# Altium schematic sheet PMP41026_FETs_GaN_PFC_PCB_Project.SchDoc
size 431 x 279 mm; Date: Not shown in title block; ApprovedBy: Not shown in title block; CheckedBy: Not shown in title block; Author: Not shown in title block; CompanyName: Not shown in title block; Engineer: Not shown in title block; Organization: Not shown in title block; Address1: Not shown in title block; Address2: Not shown in title block; Address3: Not shown in title block; Address4: Not shown in title block; DocumentNumber: 2; Revision: Use project parameter SCH_Rev; SheetNumber: 2; SheetTotal: 2; PageSetup: Record=PageOptions¦CenterHorizontal=True¦CenterVertical=True¦PrintScale=1.00¦XCorrection=1.00¦YCorrection=1.00¦PrintKind=0¦BorderSize=5000000¦LeftOffset=0¦BottomOffset=0¦Orientation=2¦PaperLength=1000¦PaperWidth=1000¦Scale=100¦PaperSource=15¦PrintQuality=600¦MediaType=1¦DitherType=10¦PaperKind=Letter¦PrintScaleMode=1
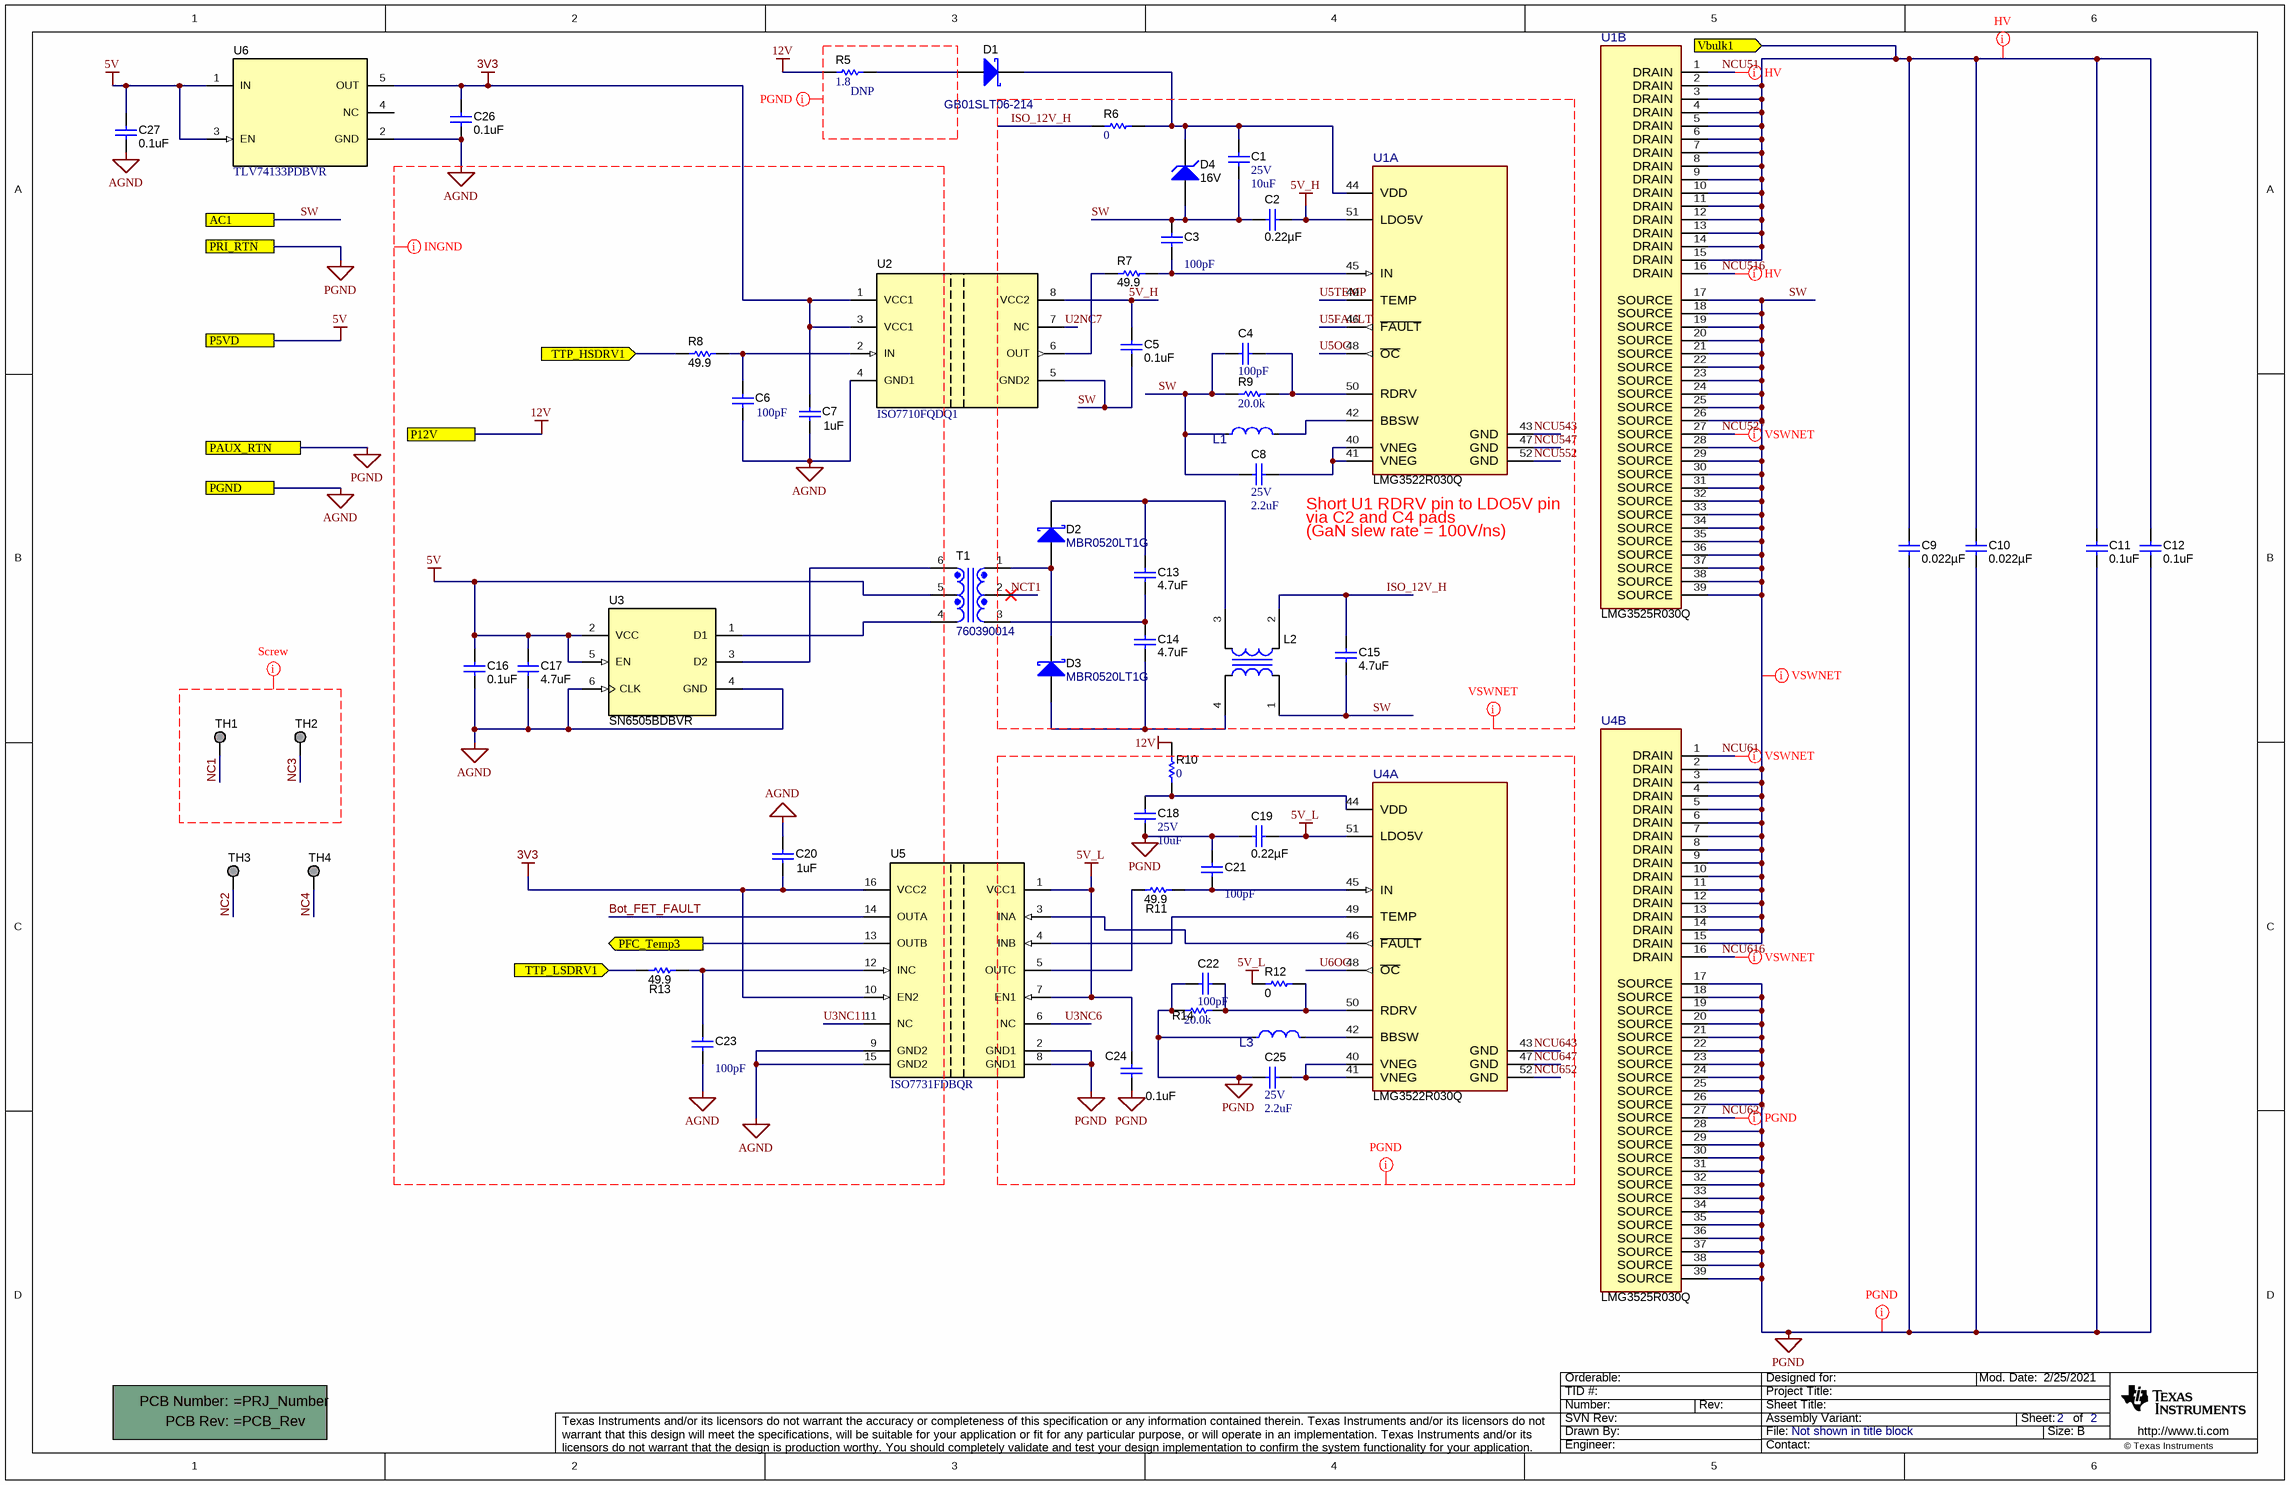
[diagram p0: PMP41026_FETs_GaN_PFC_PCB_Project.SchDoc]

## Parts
!PCB1  Printed Circuit Board  (value not drawn)  (mechanical)
C1  VDC_V: 25V  ValueDisplayed: 10uF  [1206_190]  (hidden comment: C3216X7R1E106M160AE)
C2  ValueDisplayed: 0.22µF  [0402]  (hidden comment: CL05B224KO5NNNC)
C3  ValueDisplayed: 100pF  [0402]  (hidden comment: 04025A101FAT2A)
C4  ValueDisplayed: 100pF  [0402]  (hidden comment: 04025A101FAT2A)
C5  ValueDisplayed: 0.1uF  [0402]  (hidden comment: C1005X7R1H104K050BB)
C6  ValueDisplayed: 100pF  [0402]  (hidden comment: 04025A101FAT2A)
C7  ValueDisplayed: 1uF  [0402]  (hidden comment: C1005X5R1E105K050BC)
C8  VDC_V: 25V  ValueDisplayed: 2.2uF  [0402]  (hidden comment: GRT155R61E225KE13D)
C9  ValueDisplayed: 0.022µF  [1206_190]  (hidden comment: C1206C223KDRACTU)
C10  ValueDisplayed: 0.022µF  [1206_190]  (hidden comment: C1206C223KDRACTU)
C11  ValueDisplayed: 0.1uF  [1812_254]  (hidden comment: C1812W104KDRACTU)
C12  ValueDisplayed: 0.1uF  [1812_254]  (hidden comment: C1812W104KDRACTU)
C13  ValueDisplayed: 4.7uF  [0603]  (hidden comment: C1608X5R1V475K080AC)
C14  ValueDisplayed: 4.7uF  [0603]  (hidden comment: C1608X5R1V475K080AC)
C15  ValueDisplayed: 4.7uF  [0603]  (hidden comment: C1608X5R1V475K080AC)
C16  ValueDisplayed: 0.1uF  [0402]  (hidden comment: C1005X7R1H104K050BB)
C17  ValueDisplayed: 4.7uF  [0805_HV]  (hidden comment: GCM21BR71C475KA73L)
C18  VDC_V: 25V  ValueDisplayed: 10uF  [1206_190]  (hidden comment: C3216X7R1E106M160AE)
C19  ValueDisplayed: 0.22µF  [0402]  (hidden comment: CL05B224KO5NNNC)
C20  ValueDisplayed: 1uF  [0402]  (hidden comment: C1005X5R1E105K050BC)
C21  ValueDisplayed: 100pF  [0402]  (hidden comment: 04025A101FAT2A)
C22  ValueDisplayed: 100pF  [0402]  (hidden comment: 04025A101FAT2A)
C23  ValueDisplayed: 100pF  [0402]  (hidden comment: 04025A101FAT2A)
C24  ValueDisplayed: 0.1uF  [0402]  (hidden comment: C1005X7R1H104K050BB)
C25  VDC_V: 25V  ValueDisplayed: 2.2uF  [0402]  (hidden comment: GRT155R61E225KE13D)
C26  ValueDisplayed: 0.1uF  [0402]  (hidden comment: GRM155R70J104KA01D)
C27  ValueDisplayed: 0.1uF  [0402]  (hidden comment: GRM155R70J104KA01D)
D1  GB01SLT06-214  [SMB]
D2  MBR0520LT1G  [SOD-123]
D3  MBR0520LT1G  [SOD-123]
D4  value 16V  [SOD-123]  (hidden comment: BZT52C16-7-F)
L1  SDEM20161T-4R7MS  [FP-SDEM20161T-4R7MS_SMD2-MFG]  (value not drawn)
L2  ACM2520-601-2P-T002  [TDK_ACM2520-2P]  (value not drawn)
L3  SDEM20161T-4R7MS  [FP-SDEM20161T-4R7MS_SMD2-MFG]  (value not drawn)
R5  ValueDisplayed: 1.8  [1206]  (hidden comment: CRCW12061R80JNEA)  (no BOM)
R6  ValueDisplayed: 0  [0402]  (hidden comment: ERJ-2GE0R00X)
R7  ValueDisplayed: 49.9  [0402]  (hidden comment: RC0402FR-0749R9L)
R8  ValueDisplayed: 49.9  [0402]  (hidden comment: RC0402FR-0749R9L)
R9  ValueDisplayed: 20.0k  [0402]  (hidden comment: CRCW040220K0FKED)
R10  ValueDisplayed: 0  [1206]  (hidden comment: ERJ-8GEY0R00V)
R11  ValueDisplayed: 49.9  [0402]  (hidden comment: RC0402FR-0749R9L)
R12  ValueDisplayed: 0  [0402]  (hidden comment: ERJ-2GE0R00X)  (no BOM)
R13  ValueDisplayed: 49.9  [0402]  (hidden comment: RC0402FR-0749R9L)
R14  ValueDisplayed: 20.0k  [0402]  (hidden comment: CRCW040220K0FKED)
T1  760390014  [Wurth_760390013]
TH1  (no value)  [TP_H045P075]  (no BOM)
TH2  (no value)  [TP_H045P075]  (no BOM)
TH3  (no value)  [TP_H045P075]  (no BOM)
TH4  (no value)  [TP_H045P075]  (no BOM)
U1  LMG3522R030Q  [RQS0052A-MFG]  (parts A,B of 2)
U2  ISO7710FQDQ1  [D0008B_HV]
U3  SN6505BDBVR  [DBV0006A_N]
U4  LMG3522R030Q  [RQS0052A-MFG]  (parts A,B of 2)
U5  ISO7731FDBQR  [DBQ0016A_N]
U6  TLV74133PDBVR  [DBV0005A_N]

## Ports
AC1, P5VD, P12V, PAUX_RTN, PFC_Temp3 (out), PGND, PRI_RTN, TTP_HSDRV1 (in), TTP_LSDRV1 (in), Vbulk1 (in)

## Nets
3V3: C7.1 C20.2 C26.1 U2.1(VCC1) U2.3(VCC1) U5.10(EN2) U5.16(VCC2) U6.5(OUT)
5V: C16.1 C17.1 C27.1 T1.5 U3.2(VCC) U3.5(EN) U6.1(IN) U6.3(EN) ; port P5VD
5V_H: C2.2 C5.1 U1.51(LDO5V) U2.8(VCC2)
5V_L: C19.2 C24.2 R12.1 U4.51(LDO5V) U5.1(VCC1) U5.7(EN1)
12V: R5.1 R10.1 ; port P12V
AGND: C6.2 C7.2 C16.2 C17.2 C20.1 C23.2 C26.2 C27.2 U2.4(GND1) U3.4(GND) U3.6(CLK) U5.9(GND2) U5.15(GND2) U6.2(GND) ; port PGND
PGND: C9.2 C10.2 C11.2 C12.2 C18.2 C19.1 C21.1 C22.1 C24.1 C25.2 L3.1 R14.1 U4.17(SOURCE) U4.18(SOURCE) U4.19(SOURCE) U4.20(SOURCE) U4.21(SOURCE) U4.22(SOURCE) U4.23(SOURCE) U4.24(SOURCE) U4.25(SOURCE) U4.26(SOURCE) U4.28(SOURCE) U4.29(SOURCE) U4.30(SOURCE) U4.31(SOURCE) U4.32(SOURCE) U4.33(SOURCE) U4.34(SOURCE) U4.35(SOURCE) U4.36(SOURCE) U4.37(SOURCE) U4.38(SOURCE) U4.39(SOURCE) U5.2(GND1) U5.8(GND1) ; port PRI_RTN, port PAUX_RTN
Bot_FET_FAULT: U5.14(OUTA)
ISO_12V_H: C15.1 L2.2 R6.1
NC1: TH1.1
NC2: TH3.1
NC3: TH2.1
NC4: TH4.1
NCT1: T1.2
NCU51: U1.1(DRAIN)
NCU61: U4.1(DRAIN)
NCU516: U1.16(DRAIN)
NCU527: U1.27(SOURCE)
NCU543: U1.43(GND)
NCU547: U1.47(GND)
NCU552: U1.52(GND)
NCU616: U4.16(DRAIN)
NCU627: U4.27(SOURCE)
NCU643: U4.43(GND)
NCU647: U4.47(GND)
NCU652: U4.52(GND)
PFC_Temp3: U5.13(OUTB) ; port PFC_Temp3
SW: C1.2 C2.1 C3.1 C4.1 C5.2 C8.2 C15.2 D4.2(A) L1.1 L2.1 R9.1 U1.17(SOURCE) U1.18(SOURCE) U1.19(SOURCE) U1.20(SOURCE) U1.21(SOURCE) U1.22(SOURCE) U1.23(SOURCE) U1.24(SOURCE) U1.25(SOURCE) U1.26(SOURCE) U1.28(SOURCE) U1.29(SOURCE) U1.30(SOURCE) U1.31(SOURCE) U1.32(SOURCE) U1.33(SOURCE) U1.34(SOURCE) U1.35(SOURCE) U1.36(SOURCE) U1.37(SOURCE) U1.38(SOURCE) U1.39(SOURCE) U2.5(GND2) U4.2(DRAIN) U4.3(DRAIN) U4.4(DRAIN) U4.5(DRAIN) U4.6(DRAIN) U4.7(DRAIN) U4.8(DRAIN) U4.9(DRAIN) U4.10(DRAIN) U4.11(DRAIN) U4.12(DRAIN) U4.13(DRAIN) U4.14(DRAIN) U4.15(DRAIN) ; port AC1
TTP_HSDRV1: R8.1 ; port TTP_HSDRV1
TTP_LSDRV1: R13.1 ; port TTP_LSDRV1
U2NC7: U2.7(NC)
U3NC6: U5.6(NC)
U3NC11: U5.11(NC)
U5FAULT: U1.46(~{FAULT})
U5OC: U1.48(~{OC})
U5TEMP: U1.49(TEMP)
U6OC: U4.48(~{OC})
Vbulk1: C9.1 C10.1 C11.1 C12.1 U1.2(DRAIN) U1.3(DRAIN) U1.4(DRAIN) U1.5(DRAIN) U1.6(DRAIN) U1.7(DRAIN) U1.8(DRAIN) U1.9(DRAIN) U1.10(DRAIN) U1.11(DRAIN) U1.12(DRAIN) U1.13(DRAIN) U1.14(DRAIN) U1.15(DRAIN) ; port Vbulk1
NetC1_1: C1.1 D1.1(K) D4.1(K) R6.2 U1.44(VDD)
NetC3_2: C3.2 R7.1 U1.45(IN)
NetC4_2: C4.2 R9.2 U1.50(RDRV)
NetC6_1: C6.1 R8.2 U2.2(IN)
NetC8_1: C8.1 U1.40(VNEG) U1.41(VNEG)
NetC13_1: C13.1 D2.1(K) L2.3
NetC13_2: C13.2 C14.1 T1.3
NetC14_2: C14.2 D3.2(A) L2.4
NetC18_1: C18.1 R10.2 U4.44(VDD)
NetC21_2: C21.2 R11.2 U4.45(IN)
NetC22_2: C22.2 R12.2 R14.2 U4.50(RDRV)
NetC23_1: C23.1 R13.2 U5.12(INC)
NetC25_1: C25.1 U4.40(VNEG) U4.41(VNEG)
NetD1_2: D1.2(A) R5.2
NetD2_2: D2.2(A) D3.1(K) T1.1
NetL1_2: L1.2 U1.42(BBSW)
NetL3_2: L3.2 U4.42(BBSW)
NetR7_2: R7.2 U2.6(OUT)
NetR11_1: R11.1 U5.5(OUTC)
NetT1_4: T1.4 U3.1(D1)
NetT1_6: T1.6 U3.3(D2)
NetU4_46: U4.46(~{FAULT}) U5.3(INA)
NetU4_49: U4.49(TEMP) U5.4(INB)

Not connected (* = marked no-connect by the designer): U6 4(NC)

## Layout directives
net class INGND: 3V3, 5V, 12V, AGND, Bot_FET_FAULT, U3NC11
net class VSWNET: 5V_H, ISO_12V_H, NCT1, NCU61, NCU527, NCU543, NCU547, NCU552, NCU616, SW, U2NC7, U5FAULT, U5OC, U5TEMP
net class PGND: 5V_L, (no net found under the mark), NCU627, NCU643, NCU647, NCU652, PGND, U3NC6, U6OC
net class Screw: NC1, NC3
net class HV: NCU51, NCU516, Vbulk1

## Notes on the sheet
- (near R5) DNP
- Short U1 RDRV pin to LDO5V pin
- via C2 and C4 pads
- (GaN slew rate = 100V/ns)

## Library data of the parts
!PCB1 = CMP-0003618-2: Manufacturer: Any
C1 C18 = CMP-0008692-2: CAP, CERM, 10 uF, 25 V, +/- 20%, X7R, 1206_190; Manufacturer: TDK; TaMin_C: -55°C; Polarized: N; SizeAreaWB_mm2: 10.92; Value1: Unknown; U/M: EA; Value: 10uF; TaMax_C: 125°C; SizeZ_mm: 1.9; SizeX_mm: 3.2; SizeY_mm: 1.6; Cap_Case: 1206; SizeArea_mm2: 5.12; Cap_F: 10µF; AEC Category: Q200
C2 C19 = CMP-0860563-1: CAP, CERM, 0.22 µF, 16 V,+/- 10%, X7R, 0402; Manufacturer: Samsung Electro-Mechanics; SizeX_mm: 1; Green_REACh: Incomplete; TaMin_C: -55°C; SizeArea_mm2: 0.5; TaMax_C: 125°C; U/M: EA; Green_Lifecycle: Active; SizeAreaWB_mm2: 3; VDC_V: 16V; AEC Qualified: N; SizeZ_mm: 0.6; AEC Category: Q200; Cap_F: 220nF; Value: 0.22uF
C3 C4 C6 C21-C23 = CMP-0006196-2: CAP, CERM, 100 pF, 50 V, +/- 1%, C0G/NP0, 0402; Manufacturer: AVX; TaMin_C: -55°C; Polarized: N; SizeAreaWB_mm2: 3; Value1: Unknown; U/M: EA; Value: 100pF; TaMax_C: 125°C; SizeZ_mm: 0.6; SizeX_mm: 1; SizeY_mm: 0.5; Value2: 50V; AEC Category: Q200
C5 C24 = CMP-0006297-2: CAP, CERM, 0.1 uF, 50 V, +/- 10%, X7R, 0402; Manufacturer: TDK; Alternate PartNumber: 885012205037; Alternate Manufacturer: Wurth Elektronik; Polarized: N; Value: 0.1uF; U/M: EA; Cap_F: 100nF; ESR_ohm: 0.039064; Value1: 0.039064 ohm; VDC_V: 50V; IRMS_A: 8.14669dA; TaMin_C: -55°C; TaMax_C: 125°C; SizeArea_mm2: 0.5; SizeAreaWB_mm2: 3; SizeX_mm: 1; SizeZ_mm: 0.6; AEC Category: Q200
C7 C20 = CMP-0006276-2: CAP, CERM, 1 uF, 25 V, +/- 10%, X5R, 0402; Manufacturer: TDK; Alternate PartNumber: C1005X5R1E225K050BC; TaMin_C: -55°C; Polarized: N; SizeAreaWB_mm2: 3; Value1: Unknown; U/M: EA; Value: 1uF; TaMax_C: 80°C; SizeZ_mm: 0.6; SizeX_mm: 1; SizeY_mm: 0.5; Value2: 25V; CompType: Capacitor; Cap_F: 1µF; AEC Category: Q200
C8 C25 = CMP-0006716-2: CAP, CERM, 2.2 uF, 25 V, +/- 10%, X5R, AEC-Q200 Grade 3, 0402; Manufacturer: MuRata; TaMin_C: -55°C; Polarized: N; SizeAreaWB_mm2: 3; Value1: Unknown; U/M: EA; Value: 2.2uF; TaMax_C: 85°C; SizeZ_mm: 0.6; SizeX_mm: 1; SizeY_mm: 0.5; AEC Qualified: Y; Cap_F: 2.2µF; AEC Category: Q200
C9 C10 = CMP-0084048-1: CAP, CERM, 0.022 µF, 1000 V,+/- 10%, X7R, AEC-Q200 Grade 1, 1206; Manufacturer: Kemet; Polarized: N; CompType: Capacitor; Value: 0.022uF; U/M: EA; Cap_F: 22nF; VDC_V: 1kV; Value2: 1000V; TaMin_C: -55°C; TaMax_C: 125°C; Cap_Case: 1206; SizeArea_mm2: 5.12; SizeAreaWB_mm2: 10.92; SizeX_mm: 3.2; SizeY_mm: 1.6; SizeZ_mm: 1.9; AEC Category: Q200; AEC Qualified: Y; AEC Grade: 1
C11 C12 = CMP-0009326-2: CAP, CERM, 0.1 uF, 1000 V, +/- 10%, X7R, 1812; Manufacturer: Kemet; Polarized: N; Value: 0.1uF; U/M: EA; Cap_F: 100nF; Value1: Unknown; VDC_V: 1kV; Value2: 1000V; TaMin_C: -55°C; TaMax_C: 125°C; Cap_Case: 1812; AEC Category: Q200; SizeArea_mm2: 14.4; SizeAreaWB_mm2: 23.1; SizeX_mm: 4.5; SizeY_mm: 3.2; SizeZ_mm: 2.54
C13 C14 = CMP-0007022-5: CAP, CERM, 4.7 uF, 35 V, +/- 10%, X5R, 0603; Manufacturer: TDK; TaMin_C: -55°C; ESR_ohm: 3.728m; Polarized: N; SizeAreaWB_mm2: 4.68; Value1: 0.003728 ohm; U/M: EA; Value: 4.7uF; TaMax_C: 85°C; SizeZ_mm: 1; SizeX_mm: 1.6; SizeY_mm: 0.8; Value2: 35V; SizeArea_mm2: 1.28; CompType: Capacitor; Cap_F: 4.7µF; IRMS_A: 2.69359A; AEC Category: Q200
C15 = CMP-0007022-5: CAP, CERM, 4.7 uF, 35 V, +/- 10%, X5R, 0603; Manufacturer: TDK; TaMin_C: -55°C; ESR_ohm: 3.728m; Polarized: N; SizeAreaWB_mm2: 4.68; Value1: 0.003728 ohm; U/M: EA; Value: 4.7uF; TaMax_C: 85°C; SizeZ_mm: 1; SizeX_mm: 1.6; SizeY_mm: 0.8; Value2: 35V; SizeArea_mm2: 1.28; Cap_F: 4.7µF; IRMS_A: 2.69359A; AEC Category: Q200
C16 = CMP-0006297-2: CAP, CERM, 0.1 uF, 50 V, +/- 10%, X7R, 0402; Manufacturer: TDK; Alternate PartNumber: 885012205037; Alternate Manufacturer: Wurth Elektronik; Polarized: N; CompType: Capacitor; Value: 0.1uF; U/M: EA; Cap_F: 100nF; ESR_ohm: 0.039064; Value1: 0.039064 ohm; VDC_V: 50V; IRMS_A: 8.14669dA; TaMin_C: -55°C; TaMax_C: 125°C; SizeArea_mm2: 0.5; SizeAreaWB_mm2: 3; SizeX_mm: 1; SizeZ_mm: 0.6; AEC Category: Q200
C17 = CMP-0008020-2: CAP, CERM, 4.7 uF, 16 V, +/- 10%, X7R, AEC-Q200 Grade 1, 0805; Manufacturer: MuRata; TaMin_C: -55°C; Polarized: N; SizeAreaWB_mm2: 6.75; Value1: Unknown; U/M: EA; Value: 4.7uF; TaMax_C: 125°C; SizeZ_mm: 1.45; SizeX_mm: 2; SizeY_mm: 1.25; Cap_Case: 0805; Value2: 16V; SizeArea_mm2: 2.5; AEC Qualified: Y; Cap_F: 4.7µF; AEC Grade: 1; AEC Category: Q200
C26 C27 = CMP-0006623-2: CAP, CERM, 0.1 uF, 6.3 V, +/- 10%, X7R, 0402; Manufacturer: MuRata; Polarized: N; Value: 0.1uF; U/M: EA; Cap_F: 100nF; Value1: Unknown; VDC_V: 6.3V; TaMin_C: -55°C; TaMax_C: 125°C; AEC Category: Q200; SizeArea_mm2: 0.5; SizeAreaWB_mm2: 3; SizeX_mm: 1; SizeZ_mm: 0.6
D1 = CMP-0076998-2: Diode, Schottky, 650 V, 1 A, SMB; Manufacturer: GeneSiC Semiconductor; Value1: 1A; SizeZ_mm: 2.6; Value: 650V; SizeAreaWB_mm2: 44.156; TJmax_C: 175°C; RJC_CperW: 3.55; SizeArea_mm2: 21.336; AEC Category: Q101; Value2: 2V; SizeY_mm: 3.81; SizeX_mm: 5.6
D2 D3 = CMP-0028524-2: Diode, Schottky, 20 V, 0.5 A, SOD-123; Manufacturer: ON Semiconductor; Green_REACh: Passed; TJmax_C: 125°C; Value1: 0.5A; SizeZ_mm: 1.35; Value2: 0.385V; Vf_V: 385mV; AEC Category: Q101; SizeY_mm: 1.7; Value: 20V; Io_A: 500mA; SizeX_mm: 3.85; Green_Lifecycle: Active; RJC_CperW: 150; SizeAreaWB_mm2: 13.095; SizeArea_mm2: 6.545
D4 = CMP-0005769-4: Diode, Zener, 16 V, 500 mW, AEC-Q101, SOD-123; Manufacturer: Diodes Inc.; SizeZ_mm: 1.35; AEC Qualified: Y; SizeX_mm: 3.85; AEC Category: Q101; Power_W: 500mW; SizeY_mm: 1.7; Value1: 0.5W; SizeAreaWB_mm2: 13.095; SizeArea_mm2: 6.545; RJA_CperW: 338
L1 L3 = CMP-0089347-1: 4.7µH Unshielded Inductor 1.1A 426mOhm Max 0806 (2016 Metric); Manufacturer: Cyntec; AEC Qualified: No; Material: Metal Dust; Isat: 1.26A; Test Frequency: 1MHz; DCR_ohm: 0.426; SizeZ_mm: 1mm; Tolerance_%: 20%
L2 = CMP-0013161-2: Coupled inductor, 0.2 A, 0.45 ohm, SMD; Manufacturer: TDK; SizeAreaWB_mm2: 10.5; DCR_ohm: 0.45; SizeZ_mm: 1.3; SizeX_mm: 2.5; SizeY_mm: 2; SizeArea_mm2: 5
R5 = CMP-0018623-3: RES, 1.8, 5%, 0.25 W, AEC-Q200 Grade 0, 1206; Manufacturer: Vishay-Dale; Power_W: 250mW; TempCo: 200 ppm/C; Value_Code: 1R80; Value: 1.8; EIA_Code: E24; SizeX_mm: 3.2; SizeY_mm: 1.6; SizeZ_mm: 1.35; Value2: 0.25W; SizeArea_mm2: 5.12; AEC Qualified: Y; VDC_V: 200V; AEC Category: Q200; AEC Grade: 0
R6 R12 = CMP-0026992-3: RES, 0, 5%, 0.1 W, AEC-Q200 Grade 0, 0402; Manufacturer: Panasonic; Power_W: 100mW; TempCo: 600 ppm/C; Value_Code: 0000; Value: 0; EIA_Code: E24; SizeX_mm: 1; SizeY_mm: 0.5; SizeZ_mm: 0.6; Value2: 0.1W; AEC Qualified: Y; VDC_V: 50V; AEC Category: Q200; SizeAreaWB_mm2: 3
R7 = CMP-0026738-1: RES, 49.9, 1%, 0.063 W, 0402; Manufacturer: Yageo America; CompType: Resistor; Value: 49.9; Value_Code: 49R9; Power_W: 63mW; Value2: 0.063W; VDC_V: 50V; TempCo: 100 ppm/C; EIA_Code: E96; U/M: EA; AEC Category: Q200; AEC Qualified: N; SizeArea_mm2: 0.5; SizeX_mm: 1; SizeZ_mm: 0.6
R8 R11 R13 = CMP-0026738-1: RES, 49.9, 1%, 0.063 W, 0402; Manufacturer: Yageo America; Value: 49.9; Value_Code: 49R9; Power_W: 63mW; Value2: 0.063W; VDC_V: 50V; TempCo: 100 ppm/C; EIA_Code: E96; U/M: EA; AEC Category: Q200; AEC Qualified: N; SizeArea_mm2: 0.5; SizeX_mm: 1; SizeZ_mm: 0.6
R9 R14 = CMP-0026162-1: RES, 20.0 k, 1%, 0.063 W, 0402; Manufacturer: Vishay-Dale; Power_W: 63mW; TempCo: 100 ppm/C; Value_Code: 20k0; U/M: EA; Value: 20.0k; EIA_Code: E96; Res_ohm: 20k; SizeX_mm: 1; SizeY_mm: 0.5; SizeZ_mm: 0.6; Value2: 0.063W; VDC_V: 50V; AEC Category: Q200
R10 = CMP-0018748-3: RES, 0, 5%, 0.25 W, AEC-Q200 Grade 0, 1206; Manufacturer: Panasonic; Power_W: 250mW; TempCo: 600 ppm/C; Value_Code: 0000; Value: 0; EIA_Code: E24; SizeX_mm: 3.2; SizeY_mm: 1.6; SizeZ_mm: 1.35; Value2: 0.25W; SizeArea_mm2: 5.12; AEC Qualified: Y; VDC_V: 200V; AEC Category: Q200; SizeAreaWB_mm2: 10.92
T1 = CMP-0030718-1: Transformer, 475uH, SMT; Manufacturer: Wurth Elektronik; DCR_ohm: 0.31; Lp: 475; Ind_H: 475µH
TH1-TH4 = CMP-0003719-1: Testpoint; Manufacturer: Texas Instruments; Key: TP_H0.45P0.75; CompType: Pad
U1 U4 = CMP-0089968-1: 650-V 30-mΩ GaN FET with Integrated Driver and Protection; Manufacturer: Texas Instruments; Output Voltage: 520V; Nominal Supply Current: 540uA; Min Supply Voltage: 7.5V; Standoff Height: 0mm; AEC Grade: Grade 1; Max Supply Voltage: 18V; Number Of Outputs: 1; AEC Qualified: Yes; TJmax_C: +125°C; SizeZ_mm: 1mm
U2 = CMP-0082403-1: Automotive, High Speed, Robust EMC Reinforced Single-Channel Digital Isolator, D0008B (SOIC-8); Alternate PartNumber: ISO7710FQDRQ1; Alternate Manufacturer: Texas Instruments; SizeAreaWB_mm2: 55.2; SizeZ_mm: 1.75; SizeX_mm: 6; SizeY_mm: 4.9; SizeArea_mm2: 29.4; CompType: IC; AEC Qualified: Y; AEC Category: Q200
U3 = CMP-0076095-1: Low-Noise 1 A, 420 kHz Transformer Driver, DBV0006A (SOT-23-6); Alternate PartNumber: SN6505BDBVT; Manufacturer: Texas Instruments; SizeArea_mm2: 8.12; SizeAreaWB_mm2: 14.82; SizeX_mm: 2.8; SizeY_mm: 2.9; SizeZ_mm: 1.45; CompType: IC; U/M: EA; Green_Lifecycle: Active; Green_REACh: Passed
U5 = CMP-0078719-1: High Speed, Robust EMC Triple-Channel Digital Isolators, DBQ0016A (SSOP-16); Alternate Manufacturer: Texas Instruments; SizeAreaWB_mm2: 96; SizeZ_mm: 1.75; SizeX_mm: 6; SizeY_mm: 10; SizeArea_mm2: 60; CompType: IC; AEC Qualified: N; AEC Category: Q200
U6 = CMP-0065092-2: Low-Dropout Regulator, DBV0005A (SOT-23-5); Manufacturer: Texas Instruments; SizeX_mm: 2.8; SizeY_mm: 2.9; CompType: IC; SizeZ_mm: 1.45; SizeArea_mm2: 8.12; SizeAreaWB_mm2: 14.82; U/M: EA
